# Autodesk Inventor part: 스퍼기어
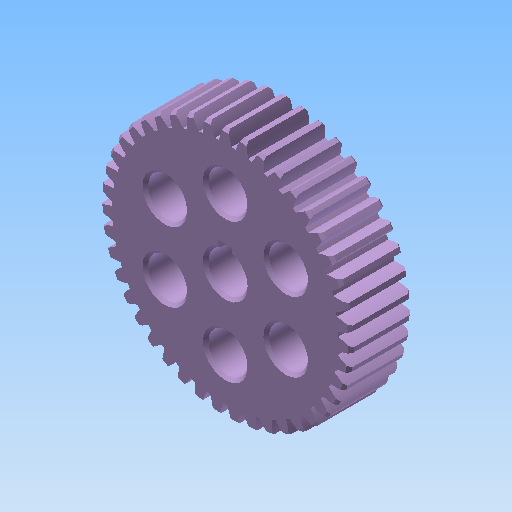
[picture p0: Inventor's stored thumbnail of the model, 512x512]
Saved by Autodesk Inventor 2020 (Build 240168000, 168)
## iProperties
CustomPartVersion: 1
Created: 2010-04
Part Number: 스퍼기어
Material: 강철, 탄소
Document SubType Name: Modeling
Designer: 진현석
Categories: <?xml version="1.0" encoding="UTF-16"?> <MemberInstance><Categories><FamilyTemplate><FamilyTemplateParameter ValueType="xs:double" Id="1" ObjectReferenceKey="da
Density: 1 g/cm^3
Appearance: 기본값(1)
Author: 진현석
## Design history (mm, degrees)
sketch "Sketch1"
  geometry: C1 r 45 at (0, 0)
  constraints: 1 centre point
  dimensions: "d0" = 90 diameter of C1 (= da_da)
extrude "Extrusion1" new body sketch "Sketch1" distance "d1" = 22 (= da_b); taper "d2" = 0 deg
workplane "Work Plane2"
feature "피치 지름" dims "d4" = 10, "d5" = 0
workplane "Work Plane8"
workplane "Work Plane9"
feature "스퍼 기어" dims "da_b" = 22, "da_d" = 86, "da_aw" = 129, "da_da" = 90, "da_df" = 81, "da_dw" = 86, angle "da_beta" = 0 deg, "da_lefttooth" = 0, "da_righttooth" = 0
chamfer "모따기1" distance "d49" = 1; stored, may be unused: second distance "d50" = 2, angle "d51" = 45 deg
sketch "스케치3"
  geometry: L1 (-2.5, 9.3)-(2.5, 9.3); L2 (2.5, 9.3)-(2.5, 3.359); L3 (2.5, 3.359)-(-2.5, 3.359); L4 (-2.5, 3.359)-(-2.5, 9.3); C1 r 7 at (0, 0); A1 r 44 centre (0, 0) between (40.958, 16.077) and (40.001, 18.327) reference; A2 r 40.5 centre (0, 0) between (38.563, 12.374) and (38.086, 13.775) reference; 1 further point
  constraints: 8 end point, 2 parallel, 1 centre point, 1 coincident, 1 horizontal, 1 midpoint, 1 perpendicular, 1 vertical alignment
  dimensions: "d52" = 14 diameter of C1; "d53" = 2.3 distance edge to line of C1 L1; "d54" = 5 distance of L1.start L1.end
extrude "돌출2" cut sketch "스케치3" extent not by distance; stored distance "d55" = 10; taper "d56" = 0 deg
sketch "스케치4"
  geometry: C1 r 7 at (0, 25); A1 r 7 centre (0, 0) between (-2.5, 6.538) and (2.5, 6.538) reference; A2 r 40.5 centre (0, 0) between (36.351, 17.857) and (35.674, 19.173) reference
  constraints: 1 centre point, 1 vertical alignment
  dimensions: "d57" = 25 distance of A1.centre C1.centre; "d58" = 14 diameter of C1
extrude "돌출3" cut sketch "스케치4" extent not by distance; stored distance "d59" = 10; taper "d60" = 0 deg
chamfer "모따기2" distance "d65" = 1; stored, may be unused: second distance "d66" = 2, angle "d67" = 45 deg
body "Solid1"
pattern_circular "원형 패턴1" dims angle "d63" = 360 deg
sketch "Sketch2"
  geometry: C1 r 45 at (0, 0) reference; C2 r 43 at (0, 0)
  constraints: 1 centre point, 1 coincident
  dimensions: "d3" = 86 diameter of C2 (= da_dw)
body "Srf1"
other parameters: "d16" = 129 (= da_aw), "d17" = 0, "d34" = 0.7306 (computed from da_z), "d39" = 0, "d41" = 0, "d43" = 129 (= da_aw), "d46" = 129 (= da_aw), "d47" = 0, "d48" = 0
